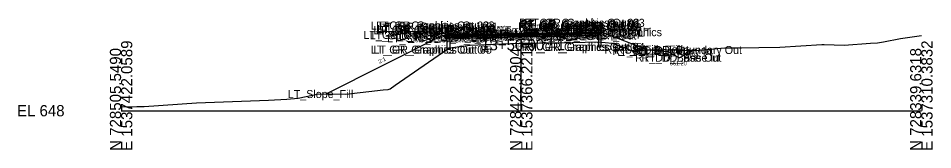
# Model space of a CAD drawing. Extents: x -26 to 1203, y -10 to 9522.
# Drawn here: x -25.7 to 202.8, y 3490.3 to 3523 of the extents above; entities that cross this region are included whole.
import ezdxf

# ---------------------------------------------------------------- set-up
doc = ezdxf.new("R2010")
doc.units = 0
for name, color, linetype in [('Default', 7, 'Continuous'), ('Exist Cross Section Cell', 7, 'Continuous'), ('Exist XS Center Line Elevation Label', 7, 'Continuous'), ('Exist XS Ground Line', 7, 'Continuous'), ('Old_Level_63', 7, 'Continuous'), ('Prop CMT Ditch DDE', 7, 'Continuous'), ('Prop CMT Guardrail Graphics', 7, 'Continuous'), ('Prop CMT Pvmt Course 1', 7, 'Continuous'), ('Prop CMT Pvmt Course 2', 7, 'Continuous'), ('Prop CMT Pvmt Course 3', 7, 'Continuous'), ('Prop CMT Pvmt Surface', 7, 'Continuous'), ('Prop CMT Pvmt Surface Overlay', 7, 'Continuous'), ('Prop CMT Pvmt Surface Shoulder', 7, 'Continuous'), ('Prop CMT Shld Paved Course 1', 7, 'Continuous'), ('Prop CMT Shld Paved Course 2', 7, 'Continuous'), ('Prop CMT Shld Paved Course 3', 7, 'Continuous'), ('Prop CMT Slope Grass', 7, 'Continuous'), ('Prop CMT Subgrade Earthwork', 7, 'Continuous'), ('Prop Superelevation  Arrow CELL', 7, 'Continuous'), ('Prop XS Ditch Slope Text', 7, 'Continuous'), ('Prop XS Ditch Standard Text', 7, 'Continuous'), ('Prop XS EOT Tick Mark', 7, 'Continuous'), ('Prop XS SE Text', 7, 'Continuous'), ('Prop XS Side Slope Text', 7, 'Continuous')]:
    doc.layers.add(name, color=color, linetype=linetype)

msp = doc.modelspace()

# ---------------------------------------------------------------- linework, layer by layer
at = {"layer": 'Exist Cross Section Cell'}
for p, q in [((100, 3500), (100, 3517.83)), ((0, 3500), (100, 3500)), ((100, 3500), (200, 3500))]:
    msp.add_line(p, q, dxfattribs=at)
at = {"layer": 'Exist XS Ground Line'}
msp.add_lwpolyline([(0, 3500.94), (3.92, 3501.03), (5.38, 3501.06), (5.74, 3501.08), (18.87, 3501.92), (36.83, 3502.64), (41.44, 3502.87), (44.24, 3503.1), (49.44, 3504.18), (56.13, 3504.08), (65.51, 3505.21), (66.75, 3505.28), (67.28, 3505.44), (68.51, 3506.39), (81.66, 3515.42), (82.15, 3515.64), (82.76, 3515.7), (87.27, 3516.29), (93.07, 3516.53), (99.52, 3516.78), (100, 3516.79), (105.42, 3516.89), (112.71, 3516.99), (119.26, 3517.12), (122.74, 3516.83), (123.99, 3516.36), (128.18, 3514.76), (131.12, 3515.14), (133.91, 3515.27), (141.46, 3515.02), (144.63, 3515.07), (150.85, 3515.64), (154.17, 3515.63), (164.61, 3515.85), (175.1, 3516.45), (175.75, 3516.46), (180.71, 3516.35), (187.33, 3516.8), (189.03, 3516.92), (190.51, 3517.13), (194.82, 3517.94), (200, 3518.75)], dxfattribs=at)
at = {"layer": 'Prop CMT Ditch DDE'}
for points in [[(131.62, 3515.16), (136.62, 3514.76), (139.47, 3513.2)], [(139.47, 3513.2), (143.16, 3515.04)]]:
    msp.add_lwpolyline(points, dxfattribs=at)
at = {"layer": 'Prop CMT Guardrail Graphics'}
for points in [[(119.98, 3521.89), (118.65, 3521.89), (118.38, 3521.59)], [(119.98, 3515.89), (119.98, 3521.89)], [(81.52, 3515.21), (81.52, 3521.21)], [(81.52, 3521.21), (82.85, 3521.21), (83.12, 3520.92)], [(83.12, 3520.34), (82.85, 3520.05), (82.18, 3520.05)], [(82.18, 3520.05), (82.18, 3515.21)], [(83.12, 3520.92), (82.85, 3520.63)], [(82.85, 3520.63), (83.12, 3520.34)], [(118.38, 3521.59), (118.65, 3521.3)], [(118.65, 3521.3), (118.38, 3521.01)], [(118.38, 3521.01), (118.65, 3520.72), (119.31, 3520.72)], [(119.31, 3520.72), (119.31, 3515.89)], [(82.18, 3515.21), (81.52, 3515.21)], [(119.31, 3515.89), (119.98, 3515.89)]]:
    msp.add_lwpolyline(points, dxfattribs=at)
at = {"layer": 'Prop CMT Pvmt Course 1'}
for points in [[(100, 3519.22), (111, 3519.42)], [(111, 3519.42), (111, 3519.17)], [(100, 3519.22), (89, 3519)], [(89, 3519), (89, 3518.75)], [(89, 3518.75), (100, 3518.97)], [(100, 3518.97), (100, 3519.22)], [(100, 3518.97), (100, 3519.22)], [(111, 3519.17), (100, 3518.97)], [(100, 3518.97), (100, 3518.97), (100, 3518.97)], [(100, 3518.97), (100, 3518.97), (100, 3518.97)]]:
    msp.add_lwpolyline(points, dxfattribs=at)
at = {"layer": 'Prop CMT Pvmt Course 2'}
for points in [[(100, 3518.97), (89, 3518.75)], [(89, 3518.54), (100, 3518.76)], [(89, 3518.75), (89, 3518.54)], [(100, 3518.97), (111, 3519.17)], [(100, 3518.76), (100, 3518.97)], [(100, 3518.76), (100, 3518.97)], [(111, 3518.96), (100, 3518.76)], [(111, 3519.17), (111, 3518.96)]]:
    msp.add_lwpolyline(points, dxfattribs=at)
at = {"layer": 'Prop CMT Pvmt Course 3'}
for points in [[(100, 3518.76), (89, 3518.54)], [(89, 3518.54), (89, 3518.17)], [(89, 3518.17), (100, 3518.39)], [(100, 3518.76), (111, 3518.96)], [(100, 3518.39), (100, 3518.76)], [(100, 3518.39), (100, 3518.76)], [(111, 3518.59), (100, 3518.39)], [(111, 3518.96), (111, 3518.59)]]:
    msp.add_lwpolyline(points, dxfattribs=at)
at = {"layer": 'Prop CMT Pvmt Surface'}
for points in [[(100, 3519.22), (111, 3519.42)], [(100, 3519.22), (89, 3519)]]:
    msp.add_lwpolyline(points, dxfattribs=at)
at = {"layer": 'Prop CMT Pvmt Surface Overlay'}
for points in [[(100, 3519.22), (111, 3519.42)], [(100, 3519.22), (89, 3519)]]:
    msp.add_lwpolyline(points, dxfattribs=at)
at = {"layer": 'Prop CMT Pvmt Surface Shoulder'}
for points in [[(111, 3519.42), (118.37, 3519.55)], [(89, 3519), (83.13, 3518.88)]]:
    msp.add_lwpolyline(points, dxfattribs=at)
at = {"layer": 'Prop CMT Shld Paved Course 1'}
for points in [[(111, 3519.42), (118.37, 3519.55), (118.62, 3519.31)], [(111, 3519.17), (111, 3519.42)], [(89, 3519), (83.13, 3518.88), (82.88, 3518.63)], [(82.88, 3518.63), (89, 3518.75)], [(89, 3518.75), (89, 3519)], [(118.62, 3519.31), (111, 3519.17)]]:
    msp.add_lwpolyline(points, dxfattribs=at)
at = {"layer": 'Prop CMT Shld Paved Course 2'}
for points in [[(89, 3518.75), (82.88, 3518.63), (82.66, 3518.41)], [(82.66, 3518.41), (89, 3518.54)], [(89, 3518.54), (89, 3518.75)], [(111, 3519.17), (118.62, 3519.31), (118.82, 3519.1)], [(111, 3518.96), (111, 3519.17)], [(118.82, 3519.1), (111, 3518.96)]]:
    msp.add_lwpolyline(points, dxfattribs=at)
at = {"layer": 'Prop CMT Shld Paved Course 3'}
for points in [[(82.66, 3518.41), (82.28, 3518.03)], [(82.28, 3518.03), (89, 3518.17)], [(89, 3518.54), (82.66, 3518.41)], [(82.66, 3518.41), (82.66, 3518.41)], [(89, 3518.17), (89, 3518.54)], [(111, 3518.96), (118.82, 3519.1)], [(111, 3518.59), (111, 3518.96)], [(119.19, 3518.73), (111, 3518.59)], [(118.82, 3519.1), (118.82, 3519.1)], [(118.82, 3519.1), (119.19, 3518.73)]]:
    msp.add_lwpolyline(points, dxfattribs=at)
at = {"layer": 'Prop CMT Slope Grass'}
for points in [[(118.37, 3519.55), (118.38, 3519.55)], [(118.37, 3519.55), (120.43, 3519.47)], [(118.38, 3519.55), (120.43, 3519.47)], [(120.43, 3519.47), (131.62, 3515.16)], [(80.12, 3518.64), (51.15, 3504.15)], [(83.12, 3518.88), (80.12, 3518.64)], [(83.13, 3518.88), (83.12, 3518.88)]]:
    msp.add_lwpolyline(points, dxfattribs=at)
at = {"layer": 'Prop CMT Subgrade Earthwork'}
for points in [[(119.19, 3518.73), (119.94, 3519.49)], [(82.28, 3518.03), (81.56, 3518.76)], [(89, 3518.17), (82.28, 3518.03)], [(100, 3518.39), (89, 3518.17)], [(100, 3518.39), (111, 3518.59)], [(111, 3518.59), (119.19, 3518.73)]]:
    msp.add_lwpolyline(points, dxfattribs=at)
at = {"layer": 'Prop Superelevation  Arrow CELL'}
for p, q in [((96.85, 3519.92), (90.85, 3519.8)), ((108.21, 3520.05), (102.21, 3519.93))]:
    msp.add_line(p, q, dxfattribs=at)
for points in [[(90.85, 3519.8), (92.34, 3520.33), (92.01, 3519.82)], [(102.21, 3519.93), (103.7, 3520.46), (103.36, 3519.96)]]:
    msp.add_lwpolyline(points, close=True, dxfattribs=at)
at = {"layer": 'Prop XS EOT Tick Mark'}
for points in [[(89, 3519), (89, 3520)], [(111, 3519.42), (111, 3520.42)]]:
    msp.add_lwpolyline(points, dxfattribs=at)

# ---------------------------------------------------------------- texts
at = {"layer": 'Default'}
msp.add_text('-', height=0.0001, dxfattribs=at).set_placement((0, 3500))
msp.add_text('-', height=0.0001, dxfattribs=at).set_placement((0, 3500))
msp.add_text('-', height=0.0001, dxfattribs=at).set_placement((0, 3500))
at = {"layer": 'Exist Cross Section Cell'}
for s, p in [('L', (90, 3517.83)), ('13+50.00 / 1', (90, 3515.03)), ('EL 648', (-26, 3498.6))]:
    msp.add_text(s, height=2.8, dxfattribs=at).set_placement(p)
for s, p in [('E 1537422.0589', (2.8, 3490)), ('E 1537366.2211', (102.8, 3490)), ('E 1537310.3832', (202.8, 3490)), ('N 728505.5490', (0, 3490)), ('N 728422.5904', (100, 3490)), ('N 728339.6318', (200, 3490))]:
    msp.add_text(s, height=2.8, rotation=90, dxfattribs=at).set_placement(p)
at = {"layer": 'Exist XS Center Line Elevation Label'}
msp.add_text('664.79', height=0.75, dxfattribs=at).set_placement((98.38, 3515.7))
at = {"layer": 'Old_Level_63'}
for s, p in [('LT_GR_Graphics Out 03', (62.41, 3520.21)), ('LT_GR_Graphics Out 02', (63.75, 3520.21)), ('LT_GR_Graphics Out 09', (63.75, 3519.63)), ('LT_GR_Graphics Out 01', (64.59, 3519.92)), ('RT_GR_Graphics Out 08', (99.23, 3520.01)), ('RT_GR_Graphics Out 02', (99.5, 3520.89)), ('RT_GR_Graphics Out 09', (99.5, 3520.3)), ('RT_GR_Graphics Out 07', (99.5, 3519.72)), ('RT_GR_Graphics Out 01', (99.79, 3520.59)), ('RT_GR_Graphics Out 06', (100.12, 3519.72)), ('RT_GR_Graphics Out 03', (100.83, 3520.89)), ('LT_GS_OS_GR_Face_Graphics', (60.58, 3517.88)), ('LT_Sub_Trench_Out_DLT', (62.12, 3517.76)), ('LT_GR_Graphics Out 06', (63.03, 3519.05)), ('LT_GR_Graphics Out 07', (63.75, 3519.05)), ('LT_GR_Graphics Out 08', (64.02, 3519.34)), ('LT_PS3_Shelf_Out', (68.65, 3517.41)), ('LT_GS_OS_CTL', (69.49, 3517.64)), ('LT_PS3_OEOP', (72.9, 3517.41)), ('LT_PS2_OEOP', (73.11, 3517.63)), ('LT_PS1_OEOP', (73.93, 3517.88)), ('LT_PV2_OEOT', (79.17, 3517.75)), ('LT_PV3_OEOT', (79.17, 3517.54)), ('LT_PV1_OEOT', (79.74, 3518)), ('LT_TM_OEOT', (79.94, 3519)), ('RT_PV1_OEEOP_W', (87.94, 3517.97)), ('LT_PV1_OEEOP_W', (87.98, 3517.97)), ('RT_Sub_OEEOP', (89.17, 3517.39)), ('LT_Sub_OEEOP', (89.21, 3517.39)), ('RT_PV2_OEEOP', (89.26, 3517.97)), ('RT_PV3_OEEOP', (89.26, 3517.76)), ('LT_PV2_OEEOP', (89.31, 3517.97)), ('LT_PV3_OEEOP', (89.31, 3517.76)), ('RT_Seek SS Fill O', (89.44, 3518.22)), ('PV1_PGL_W', (92.58, 3517.97)), ('PV1_PGL', (94.47, 3518.22)), ('RT_GS_OS_GR_Face_Graphics', (95.79, 3518.55)), ('RT_Sub_Trench_Out_DLT', (100.46, 3518.49)), ('RT_Sub_OEOT', (101.03, 3517.59)), ('RT_PV2_OEOT', (101.13, 3518.17)), ('RT_PV3_OEOT', (101.13, 3517.96)), ('RT_PV1_OEOT', (101.69, 3518.42)), ('RT_TM_OEOT', (101.9, 3519.42)), ('RT_Sub_Trench_Out', (103.35, 3517.73)), ('RT_PS3_Shelf_Out', (104.76, 3518.1)), ('RT_PS2_OEOP', (108.81, 3518.31)), ('RT_PS3_OEOP', (109.01, 3518.1)), ('RT_PS1_OEOP', (109.13, 3518.55)), ('RT_GS_OS_CTL', (109.76, 3518.47)), ('LT_Sub_Trench_Out', (66.49, 3517.03)), ('LT_Sub_OEOT', (79.08, 3517.17)), ('LT_GR_Graphics Out 04', (62.41, 3514.21)), ('LT_GR_Graphics Out 05', (63.08, 3514.21)), ('RT_GR_Graphics Out 05', (100.16, 3514.89)), ('RT_GR_Graphics Out 04', (100.83, 3514.89)), ('RT_SS_Fill_Point', (120.78, 3514.23)), ('RT_DD_Boundary In', (122.79, 3513.83)), ('RT_Slope_Fill', (123.61, 3514.23)), ('RT_DD_Boundary Out', (128.27, 3514.12)), ('RT_DD_Base Out', (128.44, 3512.2)), ('RT_DD_Base In', (130.06, 3512.2)), ('LT_Slope_Fill', (41.67, 3503.15))]:
    msp.add_text(s, height=2, dxfattribs=at).set_placement(p)
at = {"layer": 'Prop XS Ditch Slope Text'}
for rotation, p in [(333.4349, (135.88, 3513.55)), (26.5651, (142.1, 3512.97))]:
    msp.add_text('2:1', height=1, rotation=rotation, dxfattribs=at).set_placement(p)
at = {"layer": 'Prop XS Ditch Standard Text'}
msp.add_text('661.20', height=1, dxfattribs=at).set_placement((137.14, 3511.3))
at = {"layer": 'Prop XS SE Text'}
for s, rotation, p in [('0.020', 1.1458, (92.73, 3520.07)), ('0.018', 1.0413, (103.86, 3520.29))]:
    msp.add_text(s, height=1, rotation=rotation, dxfattribs=at).set_placement(p)
at = {"layer": 'Prop XS Side Slope Text'}
for s, rotation, p in [('3:1', 341.5668, (126.27, 3518.31)), ('2:1', 26.5651, (64.59, 3511.71))]:
    msp.add_text(s, height=1, rotation=rotation, dxfattribs=at).set_placement(p)

doc.saveas('drawing.dxf')
